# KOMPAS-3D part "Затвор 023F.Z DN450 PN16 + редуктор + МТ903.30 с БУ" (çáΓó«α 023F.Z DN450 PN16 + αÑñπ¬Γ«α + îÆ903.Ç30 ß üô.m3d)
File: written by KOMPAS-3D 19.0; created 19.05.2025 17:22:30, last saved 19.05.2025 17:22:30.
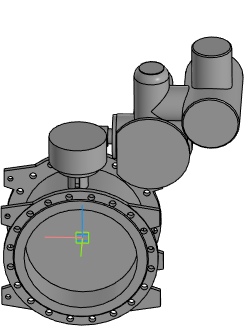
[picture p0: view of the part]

Document properties: Полное имя файла: Затвор 023F.Z DN450 PN16 + редуктор + МТ903.30 с БУ.a3d

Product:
- Part/product: Затвор 023F.Z DN450 PN16 + редуктор + МТ903.30 с БУ
    Масса: 518.234

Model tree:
1. Операция без истории:1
